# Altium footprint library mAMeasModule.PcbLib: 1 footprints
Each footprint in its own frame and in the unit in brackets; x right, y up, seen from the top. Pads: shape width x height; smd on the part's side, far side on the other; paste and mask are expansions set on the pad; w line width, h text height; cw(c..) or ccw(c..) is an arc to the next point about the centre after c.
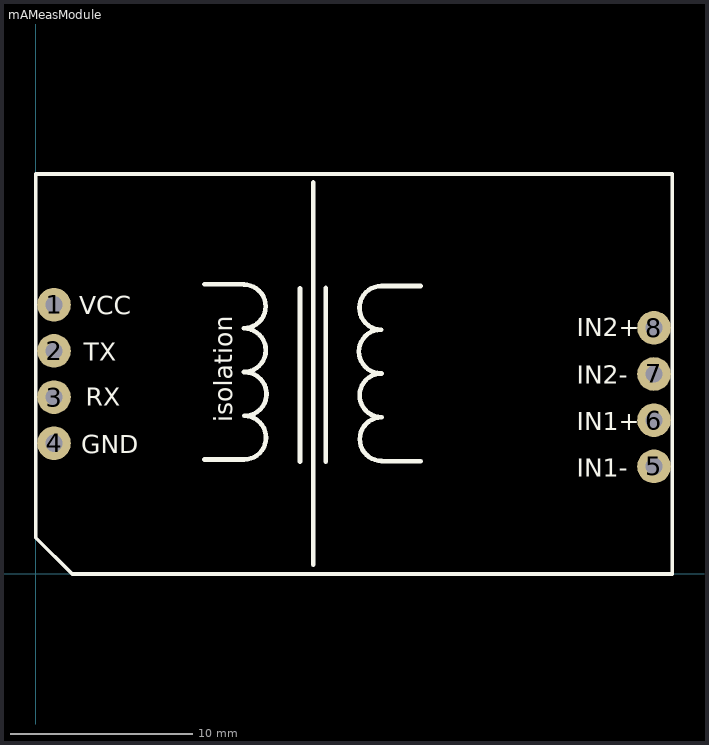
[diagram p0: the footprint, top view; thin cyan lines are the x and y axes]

## mAMeasModule [mm]
height 5
pads (8):
  round 1.85 hole 0.95: 1(1,14.81) 2(1,12.27) 3(1,9.73) 4(1,7.19) 5(34,5.92) 6(34,8.46) 7(34,11) 8(34,13.54)
Top Overlay:
  lines w0.2: 0,2 2,0 35,0 35,22 0,22 0,2
  lines w0.254: 9.28,6.298 11.46,6.298 ccw(c11.46,7.498) 11.46,8.698 ; 9.28,15.928 11.46,15.928 ; 11.44,13.518 ccw(c11.44,14.718) 11.44,15.918 ; 11.45,11.108 ccw(c11.45,12.308) 11.45,13.508 ; 11.49,8.698 ccw(c11.49,9.898) 11.49,11.098 ; 14.53,6.188 14.53,15.718 ; 15.25,0.5 15.25,21.53 ; 15.95,6.178 15.95,15.728 ; 18.97,11.038 cw(c18.97,12.238) 18.97,13.438 ; 19,6.208 21.18,6.208 ; 19,13.438 cw(c19,14.638) 19,15.838 21.18,15.838 ; 19.01,8.628 cw(c19.01,9.828) 19.01,11.028 ; 19.02,6.218 cw(c19.02,7.418) 19.02,8.618
  text "IN2+" at 29.76,13.07 h1
  text "IN2-" at 29.76,10.47 h1
  text "IN1+" at 29.76,7.92 h1
  text "IN1-" at 29.76,5.36 h1
  text "GND" at 2.507,6.63 h1
  text "RX" at 2.74,9.25 h1
  text "TX" at 2.623,11.72 h1
  text "VCC" at 2.39,14.28 h1
  text "isolation" at 10.81,8.353 h1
